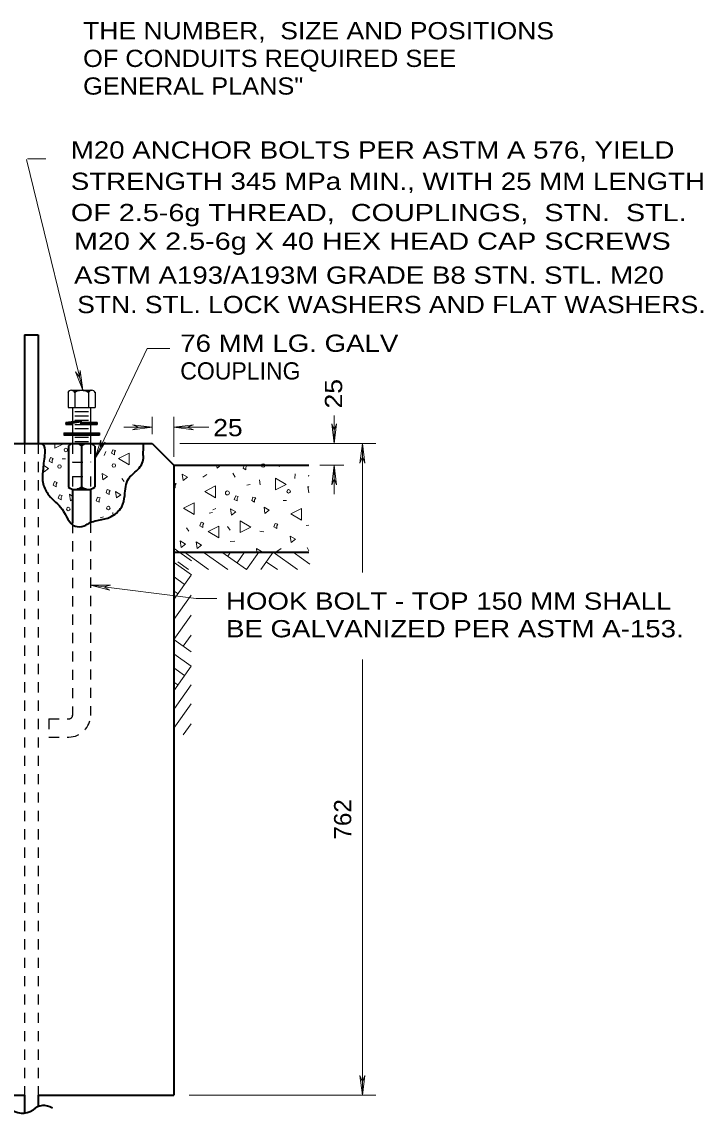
# Model space of a CAD drawing. Extents: x 312583 to 312854, y 144419 to 144597.
# Drawn here: x 312670.78 to 312700.84, y 144489.78 to 144537.93 of the extents above; entities that cross this region are included whole.
import ezdxf

# ---------------------------------------------------------------- set-up
doc = ezdxf.new("R2010")
doc.units = 0
doc.header["$LTSCALE"] = 0.3
doc.header["$PDMODE"] = 32
doc.header["$PDSIZE"] = 0.15
doc.linetypes.add('SHORT_DASHED', pattern=[2.7, 1.5, -1.2])
doc.layers.add('1', color=7, linetype='Continuous', lineweight=25)
doc.layers.add('2', color=7, linetype='Continuous', lineweight=13)

msp = doc.modelspace()

# ---------------------------------------------------------------- linework, layer by layer
at = {"layer": '1', "lineweight": 40}
for p, q in [((312670.8996, 144524.1126), (312671.4976, 144524.1126)), ((312670.8996, 144524.1126), (312670.8996, 144519.321)), ((312671.4976, 144524.1126), (312671.4976, 144519.321)), ((312659.277, 144519.321), (312676.527, 144519.321)), ((312673.4143, 144519.321), (312673.4143, 144517.297)), ((312676.527, 144519.321), (312677.4853, 144518.3626)), ((312672.8316, 144519.2136), (312672.8316, 144517.4043)), ((312673.997, 144519.2136), (312673.997, 144517.4043)), ((312677.4853, 144518.3626), (312677.4853, 144490.571)), ((312677.4853, 144518.3626), (312683.4423, 144518.3626)), ((312673.0156, 144517.3046), (312673.0156, 144515.825)), ((312673.813, 144517.3046), (312673.813, 144515.8403)), ((312677.4853, 144514.5293), (312683.4423, 144514.5293)), ((312658.3186, 144490.571), (312670.8996, 144490.571)), ((312670.8996, 144490.571), (312670.8996, 144489.789)), ((312671.4976, 144490.571), (312671.4976, 144490.0726)), ((312671.4976, 144490.571), (312677.4853, 144490.571))]:
    msp.add_line(p, q, dxfattribs=at)
at = {"layer": '1'}
for p, q in [((312672.8163, 144521.5826), (312672.8163, 144520.9156)), ((312672.962, 144521.6746), (312673.859, 144521.6746)), ((312673.1153, 144521.5826), (312673.1153, 144520.9156)), ((312673.7133, 144521.5826), (312673.7133, 144520.9156)), ((312674.0123, 144521.5826), (312674.0123, 144520.9156)), ((312672.8163, 144520.9156), (312674.0123, 144520.9156)), ((312673.0156, 144520.9156), (312673.0156, 144519.321)), ((312673.813, 144520.9156), (312673.813, 144519.321)), ((312673.1153, 144520.7316), (312673.7133, 144520.7316)), ((312673.1153, 144520.54), (312673.7133, 144520.54)), ((312673.1153, 144520.356), (312673.7133, 144520.356)), ((312672.6246, 144519.7886), (312674.204, 144519.7886)), ((312672.6246, 144519.7886), (312672.6246, 144519.6966)), ((312672.7243, 144520.264), (312672.7243, 144520.1643)), ((312673.1153, 144520.1643), (312673.7133, 144520.1643)), ((312673.1153, 144519.9803), (312673.7133, 144519.9803)), ((312673.353, 144520.1643), (312674.1043, 144520.1643)), ((312673.3836, 144520.264), (312674.1043, 144520.264)), ((312674.1043, 144520.2563), (312674.1043, 144520.1643)), ((312674.204, 144519.7886), (312674.204, 144519.6966)), ((312672.6246, 144519.7656), (312674.204, 144519.7656)), ((312672.6246, 144519.7426), (312674.204, 144519.7426)), ((312672.6246, 144519.712), (312674.204, 144519.712)), ((312672.6246, 144519.6966), (312674.204, 144519.6966)), ((312673.0156, 144519.321), (312673.813, 144519.321)), ((312673.1153, 144519.597), (312673.7133, 144519.597)), ((312673.1153, 144519.413), (312673.7133, 144519.413)), ((312673.123, 144519.321), (312673.7056, 144519.321))]:
    msp.add_line(p, q, dxfattribs=at)
at = {"layer": '1', "linetype": 'SHORT_DASHED'}
for p, q in [((312670.8996, 144519.321), (312670.8996, 144490.571)), ((312671.4976, 144519.321), (312671.4976, 144490.571)), ((312673.0156, 144519.321), (312673.0156, 144518.5083)), ((312673.813, 144519.321), (312673.813, 144518.5083)), ((312673.0156, 144518.5083), (312673.813, 144518.5083)), ((312673.0156, 144517.872), (312673.813, 144517.872)), ((312673.0156, 144517.872), (312673.0156, 144517.3046)), ((312673.813, 144517.872), (312673.813, 144517.3046)), ((312673.123, 144517.297), (312673.7056, 144517.297)), ((312673.0156, 144515.825), (312673.0156, 144507.3303)), ((312673.813, 144515.8403), (312673.813, 144507.3303)), ((312671.973, 144507.177), (312671.973, 144506.372)), ((312671.973, 144507.177), (312672.8546, 144507.177)), ((312671.973, 144506.372), (312672.8546, 144506.372))]:
    msp.add_line(p, q, dxfattribs=at)
at = {"layer": '1'}
for points in [[(312673.0003, 144521.6746), (312673.3376, 144521.667), (312673.2763, 144521.6593), (312673.2456, 144521.6516), (312673.1766, 144521.6286), (312673.1153, 144521.5826), (312673.0923, 144521.621), (312673.0693, 144521.644), (312673.0156, 144521.667), (312673.307, 144521.667), (312673.2226, 144521.6516), (312673.169, 144521.621), (312673.123, 144521.5903), (312673.0693, 144521.6363), (312673.0386, 144521.6593), (312673.2763, 144521.667), (312673.192, 144521.6363), (312673.123, 144521.598), (312673.054, 144521.6593), (312673.2456, 144521.6593), (312673.1153, 144521.6056), (312673.0616, 144521.6516), (312673.2226, 144521.6593), (312673.1153, 144521.6133), (312673.077, 144521.6516), (312673.1996, 144521.6516), (312673.1153, 144521.6286), (312673.0923, 144521.644), (312673.169, 144521.6516), (312673.123, 144521.6286), (312673.1076, 144521.644), (312673.1383, 144521.644), (312673.1153, 144521.6363)], [(312673.8283, 144521.6746), (312673.491, 144521.667), (312673.5446, 144521.6593), (312673.583, 144521.6516), (312673.6443, 144521.6286), (312673.7133, 144521.5826), (312673.7363, 144521.621), (312673.7593, 144521.644), (312673.813, 144521.667), (312673.514, 144521.667), (312673.5983, 144521.6516), (312673.6596, 144521.621), (312673.7056, 144521.5903), (312673.7593, 144521.6363), (312673.79, 144521.6593), (312673.5523, 144521.667), (312673.6366, 144521.6363), (312673.7056, 144521.598), (312673.7746, 144521.6593), (312673.583, 144521.6593), (312673.7133, 144521.6056), (312673.7593, 144521.6516), (312673.5983, 144521.6593), (312673.7133, 144521.6133), (312673.7516, 144521.6516), (312673.629, 144521.6516), (312673.7133, 144521.6286), (312673.7363, 144521.644), (312673.6596, 144521.6516), (312673.7056, 144521.6286), (312673.721, 144521.644), (312673.6826, 144521.644), (312673.7056, 144521.6363)], [(312672.7243, 144520.264), (312673.4143, 144520.356), (312673.353, 144520.1643)], [(312673.0156, 144520.1643), (312672.7243, 144520.1796), (312672.732, 144520.2486), (312673.3913, 144520.3406), (312673.3683, 144520.2716), (312673.008, 144520.218), (312673.0003, 144520.1796), (312672.7396, 144520.1873), (312672.7396, 144520.241), (312673.376, 144520.3253), (312673.3606, 144520.2793), (312672.9926, 144520.218), (312672.985, 144520.1873), (312672.7473, 144520.195), (312672.7473, 144520.2256), (312673.353, 144520.31), (312673.353, 144520.2946), (312673.0003, 144520.2256), (312672.9773, 144520.218), (312672.9006, 144520.2026), (312672.7626, 144520.2103), (312673.3376, 144520.3023), (312672.8546, 144520.2103)], [(312673.3836, 144520.264), (312672.7243, 144520.1643), (312673.0156, 144520.1643)], [(312673.3683, 144520.1796), (312674.089, 144520.1796), (312674.089, 144520.2486), (312673.399, 144520.2486), (312673.376, 144520.1873), (312674.0813, 144520.1873), (312674.0813, 144520.2333), (312673.4066, 144520.2333), (312673.3913, 144520.195), (312674.066, 144520.2026), (312674.0583, 144520.218), (312674.0506, 144520.2256), (312673.4066, 144520.2256), (312673.399, 144520.2103), (312674.0506, 144520.2103)], [(312673.1996, 144519.3133), (312673.629, 144519.3133), (312673.583, 144519.3056), (312673.537, 144519.2903), (312673.491, 144519.2673), (312673.4603, 144519.252), (312673.4143, 144519.229), (312673.4143, 144519.2213), (312673.33, 144519.275), (312673.261, 144519.298), (312673.2226, 144519.3133), (312673.5983, 144519.3133), (312673.5676, 144519.3056), (312673.537, 144519.298), (312673.491, 144519.2826), (312673.445, 144519.2596), (312673.4296, 144519.2443), (312673.4143, 144519.229), (312673.3376, 144519.275), (312673.261, 144519.3056), (312673.5446, 144519.3056), (312673.4756, 144519.2826), (312673.4143, 144519.2443), (312673.2916, 144519.298), (312673.514, 144519.3056), (312673.4143, 144519.2366), (312673.3146, 144519.298), (312673.4986, 144519.298), (312673.422, 144519.2596), (312673.353, 144519.2903), (312673.468, 144519.2903), (312673.4143, 144519.275), (312673.3453, 144519.2826), (312673.3913, 144519.2596), (312673.399, 144519.2903), (312673.4066, 144519.252), (312673.4373, 144519.2826), (312673.4526, 144519.2826), (312673.4756, 144519.2903)]]:
    msp.add_lwpolyline(points, dxfattribs=at)
at = {"layer": '1', "lineweight": 40}
msp.add_lwpolyline([(312673.1996, 144517.297), (312673.629, 144517.297), (312673.583, 144517.3046), (312673.537, 144517.32), (312673.491, 144517.343), (312673.4603, 144517.3583), (312673.4143, 144517.389), (312673.4143, 144517.389), (312673.33, 144517.343), (312673.261, 144517.3123), (312673.2226, 144517.3046), (312673.5983, 144517.297), (312673.5676, 144517.3046), (312673.537, 144517.3123), (312673.491, 144517.3276), (312673.445, 144517.3506), (312673.4296, 144517.366), (312673.4143, 144517.3813), (312673.3376, 144517.3353), (312673.261, 144517.3046), (312673.5446, 144517.3046), (312673.4756, 144517.3276), (312673.4143, 144517.366), (312673.2916, 144517.3123), (312673.514, 144517.3046), (312673.4143, 144517.3736), (312673.3146, 144517.3123), (312673.4986, 144517.3123), (312673.422, 144517.3583), (312673.353, 144517.32), (312673.468, 144517.32), (312673.4143, 144517.3353), (312673.3453, 144517.3276), (312673.3913, 144517.3506), (312673.399, 144517.3276), (312673.4066, 144517.366), (312673.4373, 144517.3353), (312673.4526, 144517.3276), (312673.4756, 144517.3276)], dxfattribs=at)
at = {"layer": '1'}
for centre, radius, start, end in [((312672.9638, 144521.5076), 0.1659, 25.60064, 154.39936), ((312673.4127, 144521.1512), 0.5224, 55.04559, 124.95441), ((312673.8617, 144521.5076), 0.1659, 25.60064, 154.39936), ((312673.1206, 144518.8631), 0.4545, 50.00693, 129.99306), ((312673.7048, 144518.8631), 0.4545, 50.00694, 129.99307)]:
    msp.add_arc(centre, radius, start, end, dxfattribs=at)
at = {"layer": '1', "lineweight": 40}
for centre, radius, start, end in [((312673.1206, 144517.7493), 0.4545, 230.00694, 309.99307), ((312673.7048, 144517.7493), 0.4545, 230.00693, 309.99306), ((312670.8004, 144490.5843), 0.8027, 225.84295, 305.84934), ((312671.7467, 144489.403), 0.713, 58.11032, 131.90694)]:
    msp.add_arc(centre, radius, start, end, dxfattribs=at)
at = {"layer": '1', "linetype": 'SHORT_DASHED'}
for radius in [0.9583, 0.16]:
    msp.add_arc((312672.8537, 144507.3341), radius, 270, 0, dxfattribs=at)
at = {"layer": '1', "lineweight": 40}
msp.add_spline([(312671.674, 144519.321), (312671.743, 144519.2366), (312671.7813, 144518.7996), (312671.7046, 144518.1326), (312671.72, 144517.5423), (312671.973, 144517.044), (312672.5556, 144516.423), (312673.1306, 144515.6793), (312673.5293, 144515.6946), (312673.7976, 144515.8326), (312674.0966, 144515.9246), (312674.6333, 144516.0626), (312675.1853, 144516.538), (312675.3156, 144517.0286), (312675.4843, 144517.7723), (312675.768, 144518.056), (312676.136, 144518.608), (312676.136, 144518.907), (312676.1513, 144519.16), (312676.1513, 144519.321)], degree=3, dxfattribs=at)
at = {"layer": '2'}
for p, q in [((312670.9763, 144531.8483), (312673.4756, 144521.6746)), ((312671.835, 144531.8866), (312671.0223, 144531.8866)), ((312673.146, 144522.4873), (312673.3223, 144522.2496)), ((312673.4756, 144521.6746), (312673.146, 144522.4873)), ((312673.353, 144522.541), (312673.3223, 144522.2496)), ((312673.4756, 144521.6746), (312673.353, 144522.541)), ((312676.527, 144519.7426), (312676.527, 144520.5016)), ((312677.4853, 144518.7306), (312677.4853, 144520.5016)), ((312684.5616, 144519.321), (312684.5616, 144520.563)), ((312675.285, 144520.0416), (312676.527, 144520.0416)), ((312675.6606, 144520.149), (312675.9366, 144520.0416)), ((312676.527, 144520.0416), (312675.6606, 144520.149)), ((312675.6606, 144519.9343), (312675.9366, 144520.0416)), ((312676.527, 144520.0416), (312675.6606, 144519.9343)), ((312677.4853, 144520.0416), (312678.3516, 144520.149)), ((312677.4853, 144520.0416), (312679.034, 144520.0416)), ((312677.4853, 144520.0416), (312678.3516, 144519.9343)), ((312678.3516, 144520.149), (312678.0756, 144520.0416)), ((312678.3516, 144519.9343), (312678.0756, 144520.0416)), ((312684.4543, 144520.1873), (312684.5616, 144519.9113)), ((312684.5616, 144519.321), (312684.4543, 144520.1873)), ((312684.669, 144520.1873), (312684.5616, 144519.9113)), ((312684.5616, 144519.321), (312684.669, 144520.1873)), ((312673.997, 144518.6463), (312674.2625, 144519.4757)), ((312673.997, 144518.6463), (312674.4567, 144519.3839)), ((312674.2625, 144519.4757), (312674.2501, 144519.1783)), ((312674.4567, 144519.3839), (312674.2501, 144519.1783)), ((312677.7536, 144519.321), (312686.4016, 144519.321)), ((312685.8036, 144519.321), (312685.6963, 144518.4546)), ((312685.8036, 144519.321), (312685.911, 144518.4546)), ((312685.8036, 144513.64), (312685.8036, 144519.321)), ((312674.48, 144518.9683), (312674.4033, 144518.7996)), ((312672.5633, 144518.6463), (312672.709, 144518.654)), ((312679.3713, 144518.3626), (312679.3943, 144518.2323)), ((312679.3943, 144518.2323), (312679.563, 144518.3626)), ((312682.1313, 144518.3166), (312682.1926, 144518.3626)), ((312682.1313, 144518.355), (312682.1313, 144518.3166)), ((312683.933, 144518.3626), (312684.9833, 144518.3626)), ((312684.5616, 144518.3626), (312684.4543, 144517.4963)), ((312684.5616, 144517.0823), (312684.5616, 144518.3626)), ((312684.5616, 144518.3626), (312684.669, 144517.4963)), ((312685.6963, 144518.4546), (312685.8036, 144518.7306)), ((312685.911, 144518.4546), (312685.8036, 144518.7306)), ((312671.7353, 144518.2553), (312671.7583, 144518.079)), ((312678.942, 144517.964), (312678.7656, 144517.8336)), ((312680.092, 144518.01), (312680.184, 144517.8413)), ((312682.8213, 144517.7876), (312682.8443, 144517.9793)), ((312675.1853, 144517.78), (312675.2926, 144517.642)), ((312680.7053, 144517.481), (312680.851, 144517.5193)), ((312681.265, 144517.7186), (312681.288, 144517.504)), ((312684.4543, 144517.4963), (312684.5616, 144517.7723)), ((312684.669, 144517.4963), (312684.5616, 144517.7723)), ((312683.4346, 144517.1436), (312683.4423, 144517.1436)), ((312672.4713, 144516.5303), (312672.4636, 144516.5226)), ((312672.9236, 144516.7986), (312672.985, 144516.8446)), ((312679.2103, 144516.3923), (312679.3406, 144516.4613)), ((312682.3076, 144516.8063), (312682.4533, 144516.814)), ((312674.2346, 144516.0473), (312674.3803, 144516.0856)), ((312674.7943, 144516.2773), (312674.8096, 144516.147)), ((312679.0416, 144516.2543), (312679.1873, 144516.285)), ((312678.0373, 144515.6026), (312678.1446, 144515.457)), ((312679.8466, 144515.6563), (312679.9693, 144515.503)), ((312681.2803, 144515.4646), (312681.449, 144515.4263)), ((312683.3273, 144515.71), (312683.4423, 144515.7176)), ((312679.9693, 144515.0046), (312680.1763, 144515.0123)), ((312677.5006, 144514.698), (312678.2596, 144514.1536)), ((312679.0186, 144513.7626), (312677.953, 144514.5293)), ((312679.862, 144513.7626), (312678.8193, 144514.5063)), ((312680.6976, 144513.7626), (312679.609, 144514.537)), ((312679.9846, 144514.5293), (312679.862, 144514.353)), ((312680.6056, 144514.5293), (312680.276, 144514.0616)), ((312681.2343, 144514.5293), (312680.6976, 144513.7626)), ((312681.863, 144514.5293), (312681.3186, 144513.7626)), ((312682.9363, 144513.7626), (312681.863, 144514.5293)), ((312682.2156, 144514.6903), (312682.0316, 144514.56)), ((312683.4806, 144514.0003), (312682.7446, 144514.5293)), ((312683.3656, 144514.7363), (312683.4423, 144514.5906)), ((312677.5006, 144514.0693), (312678.2596, 144513.525)), ((312678.137, 144513.7626), (312677.654, 144514.1076)), ((312682.0546, 144513.7626), (312681.564, 144514.1076)), ((312673.813, 144513.0726), (312674.6563, 144512.858)), ((312673.813, 144513.0726), (312674.687, 144513.0726)), ((312674.687, 144513.0726), (312674.3956, 144513.0036)), ((312678.2443, 144513.5096), (312677.4853, 144512.4363)), ((312677.5006, 144513.4406), (312677.9606, 144513.111)), ((312674.6563, 144512.858), (312674.3956, 144513.0036)), ((312678.2443, 144512.628), (312677.4853, 144511.5546)), ((312677.5006, 144512.812), (312677.6693, 144512.6893)), ((312678.2443, 144511.7463), (312677.4853, 144510.6806)), ((312677.4853, 144510.6806), (312678.2443, 144510.1363)), ((312678.2443, 144510.8646), (312677.8993, 144510.3816)), ((312677.4853, 144510.052), (312678.2443, 144509.5076)), ((312685.8036, 144490.571), (312685.8036, 144509.799)), ((312678.2443, 144509.5076), (312677.4776, 144508.419)), ((312677.4853, 144509.4233), (312677.953, 144509.0936)), ((312677.4853, 144508.7946), (312677.654, 144508.672)), ((312678.2443, 144508.6796), (312677.5083, 144507.637)), ((312678.2443, 144507.8363), (312677.4853, 144506.763)), ((312678.2443, 144506.9546), (312677.8993, 144506.4716)), ((312685.6963, 144491.4373), (312685.8036, 144491.1613)), ((312685.8036, 144490.571), (312685.6963, 144491.4373)), ((312685.911, 144491.4373), (312685.8036, 144491.1613)), ((312685.8036, 144490.571), (312685.911, 144491.4373)), ((312678.1676, 144490.571), (312686.4016, 144490.571))]:
    msp.add_line(p, q, dxfattribs=at)
for points in [[(312677.3124, 144523.5175), (312676.3134, 144523.5175), (312673.997, 144518.6463)], [(312672.2336, 144519.3133), (312672.2336, 144519.114), (312672.617, 144519.3056)], [(312671.7583, 144518.079), (312671.95, 144518.2246), (312671.743, 144518.3473)], [(312680.5826, 144518.355), (312680.5366, 144518.24), (312680.6593, 144518.1633), (312680.6593, 144518.2706)], [(312680.6593, 144518.2706), (312680.7053, 144518.355), (312680.6823, 144518.3626)], [(312683.4423, 144517.9333), (312683.427, 144517.895), (312683.4423, 144517.8796)], [(312677.539, 144517.481), (312677.585, 144517.5653), (312677.4853, 144517.596)], [(312677.4853, 144517.4043), (312677.539, 144517.3736), (312677.539, 144517.481)], [(312683.4423, 144517.4043), (312683.3963, 144517.4273), (312683.4346, 144517.1436)], [(312672.985, 144517.021), (312672.8853, 144517.0823), (312672.9236, 144516.7986)], [(312681.311, 144514.5293), (312681.357, 144514.56), (312681.127, 144514.698), (312681.15, 144514.5293)], [(312679.379, 144512.4823), (312678.4666, 144512.4823), (312673.813, 144513.0726)]]:
    msp.add_lwpolyline(points, dxfattribs=at)
for points in [[(312674.8633, 144518.9376), (312674.9093, 144519.022), (312674.7943, 144519.0526), (312674.733, 144518.8993), (312674.8633, 144518.8303)], [(312675.515, 144518.378), (312675.515, 144518.8916), (312675.0473, 144518.6616)], [(312672.111, 144518.585), (312672.1646, 144518.6693), (312672.042, 144518.7), (312671.9883, 144518.5466), (312672.111, 144518.4776)], [(312674.3573, 144517.7186), (312674.5566, 144517.8643), (312674.319, 144518.0023)], [(312677.8916, 144517.688), (312678.0833, 144517.8336), (312677.8533, 144517.9716)], [(312672.2873, 144517.527), (312672.3333, 144517.6113), (312672.2183, 144517.642), (312672.157, 144517.4886), (312672.2873, 144517.4196)], [(312679.3176, 144516.929), (312679.3176, 144517.4503), (312678.85, 144517.2126)], [(312681.978, 144517.7953), (312681.978, 144517.274), (312682.4456, 144517.5116)], [(312672.5096, 144516.9443), (312672.5556, 144517.0286), (312672.4406, 144517.067), (312672.3793, 144516.9136), (312672.5096, 144516.8446)], [(312674.1886, 144516.837), (312674.2346, 144516.9213), (312674.1196, 144516.952), (312674.0583, 144516.7986), (312674.1886, 144516.7296)], [(312674.6256, 144517.1743), (312674.6716, 144517.2586), (312674.549, 144517.297), (312674.4953, 144517.1436), (312674.6256, 144517.0746)], [(312674.9553, 144516.9213), (312675.147, 144517.067), (312674.917, 144517.2126)], [(312680.2836, 144516.8983), (312680.3296, 144516.9826), (312680.2146, 144517.0133), (312680.1533, 144516.86), (312680.2836, 144516.791)], [(312681.0503, 144516.8446), (312681.0963, 144516.929), (312680.9736, 144516.9596), (312680.92, 144516.8063), (312681.0503, 144516.7373)], [(312678.3746, 144516.193), (312678.3746, 144516.7143), (312677.907, 144516.4766)], [(312680.023, 144516.1623), (312680.2146, 144516.308), (312679.9846, 144516.446)], [(312681.5026, 144516.239), (312681.6943, 144516.3846), (312681.4643, 144516.5226)], [(312683.1126, 144515.9476), (312683.1126, 144516.4613), (312682.645, 144516.2236)], [(312678.7656, 144515.733), (312678.8116, 144515.8096), (312678.689, 144515.848), (312678.6353, 144515.6946), (312678.7656, 144515.6256)], [(312679.4633, 144515.1656), (312679.4633, 144515.6793), (312678.9956, 144515.4416)], [(312680.414, 144515.917), (312680.414, 144515.4033), (312680.8816, 144515.6333)], [(312682.0316, 144515.687), (312682.0776, 144515.7713), (312681.9626, 144515.802), (312681.9013, 144515.6486), (312682.0316, 144515.5796)], [(312677.8073, 144514.744), (312677.999, 144514.8896), (312677.769, 144515.0276)], [(312678.5203, 144514.698), (312678.712, 144514.8436), (312678.4743, 144514.9893)], [(312682.668, 144514.9586), (312682.8596, 144515.1043), (312682.622, 144515.2423)]]:
    msp.add_lwpolyline(points, close=True, dxfattribs=at)
for centre, radius in [((312672.7185, 144519.0396), 0.0784), ((312672.4396, 144518.3104), 0.0784), ((312674.8364, 144518.3535), 0.0784), ((312679.8487, 144517.1431), 0.0865), ((312682.5489, 144517.2133), 0.0784), ((312672.8287, 144516.432), 0.0784), ((312674.5959, 144516.4761), 0.0784)]:
    msp.add_circle(centre, radius, dxfattribs=at)
msp.add_point((312681.426, 144518.355), dxfattribs=at)

# ---------------------------------------------------------------- texts
for s, width, p in [('THE NUMBER,  SIZE AND POSITIONS', 1.15, (312673.4809, 144537.1558)), ('OF CONDUITS REQUIRED SEE', 1.1, (312673.4809, 144535.9358)), ('GENERAL PLANS"', 1.1, (312673.4809, 144534.7158)), ('M20 ANCHOR BOLTS PER ASTM A 576, YIELD', 1.2, (312672.939, 144531.8933)), ('STRENGTH 345 MPa MIN., WITH 25 MM LENGTH', 1.2, (312672.939, 144530.5133)), ('OF 2.5-6g THREAD,  COUPLINGS,  STN.  STL.', 1.25, (312672.939, 144529.1333)), ('M20 X 2.5-6g X 40 HEX HEAD CAP SCREWS ', 1.25, (312673.0755, 144527.8712)), ('ASTM A193/A193M GRADE B8 STN. STL. M20', 1.2, (312673.0827, 144526.3733)), ('STN. STL. LOCK WASHERS AND FLAT WASHERS. ', 1.15, (312673.2193, 144525.0753)), ('76 MM LG. GALV', 1.2, (312677.7673, 144523.368)), ('25 ', 1.15, (312679.221, 144519.6453)), ('HOOK BOLT - TOP 150 MM SHALL', 1.2, (312679.7858, 144511.9948)), ('BE GALVANIZED PER ASTM A-153.', 1.2, (312679.7858, 144510.7748))]:
    msp.add_text(s, height=0.76, dxfattribs=dict(at, width=width)).set_placement(p)
msp.add_text('COUPLING', height=0.76, dxfattribs=at).set_placement((312677.7673, 144522.148))
for s, width, p in [('25 ', 1.15, (312684.9109, 144520.8703)), ('762', 1.05, (312685.3133, 144501.8535))]:
    msp.add_text(s, height=0.76, rotation=90, dxfattribs=dict(at, width=width)).set_placement(p)

doc.saveas('drawing.dxf')
